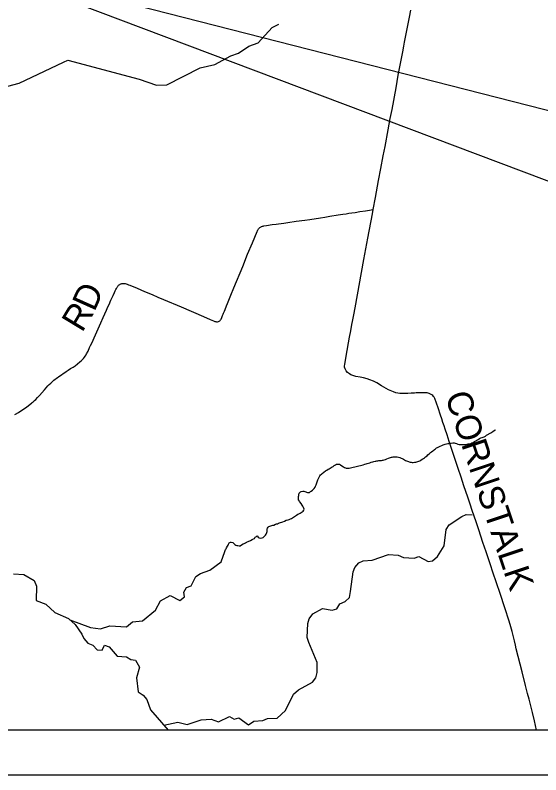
# Model space of a CAD drawing. Extents: x -19.5 to 44.1, y 0 to 22.
# Drawn here: x 5.392 to 6.569, y 14.347 to 16.047 of the extents above; entities that cross this region are included whole.
import ezdxf

# ---------------------------------------------------------------- set-up
doc = ezdxf.new("R2010")
doc.units = 0
for name, color, linetype in [('GM_X_Minor_River', 7, 'Continuous'), ('GM_X_Township_Road', 7, 'Continuous'), ('GM_X_Township_Road_Text', 7, 'Continuous'), ('SH_Data', 7, 'Continuous'), ('SH_Text', 7, 'Continuous')]:
    doc.layers.add(name, color=color, linetype=linetype)

msp = doc.modelspace()

# ---------------------------------------------------------------- linework, layer by layer
at = {"layer": 'GM_X_Minor_River'}
for points in [[(5.8753, 15.9562), (5.8924, 15.9617), (5.9155, 15.9779), (5.9366, 15.985), (5.9677, 16.0192), (5.9822, 16.0269)], [(5.1646, 15.8833), (5.2068, 15.901), (5.2193, 15.9), (5.2744, 15.8847), (5.3301, 15.8816), (5.3647, 15.8855), (5.4009, 15.8946), (5.5005, 15.9422), (5.5101, 15.9466), (5.6698, 15.9036), (5.709, 15.8906), (5.7318, 15.8909), (5.8065, 15.9292), (5.8393, 15.9365), (5.8753, 15.9562)], [(6.3064, 15.055), (6.309, 15.0569), (6.3109, 15.0588), (6.3144, 15.0614), (6.3163, 15.0633), (6.3194, 15.0655), (6.3224, 15.0682), (6.3243, 15.0697), (6.3274, 15.072), (6.3293, 15.0738), (6.3312, 15.0753), (6.3335, 15.0768), (6.3358, 15.0787), (6.3377, 15.0799), (6.3411, 15.0814), (6.3438, 15.0825), (6.3472, 15.084), (6.3503, 15.0855), (6.3526, 15.0862), (6.3552, 15.087), (6.3606, 15.0884), (6.3632, 15.0888), (6.3655, 15.0895), (6.3682, 15.0895), (6.3724, 15.0899), (6.375, 15.0899), (6.3773, 15.0891), (6.3803, 15.0883), (6.383, 15.0875), (6.386, 15.0867), (6.3879, 15.0863), (6.3906, 15.0863), (6.3948, 15.0863), (6.3974, 15.0867), (6.4009, 15.0866), (6.4039, 15.0874), (6.4062, 15.0877), (6.4081, 15.0877), (6.4123, 15.0888), (6.4146, 15.09), (6.4176, 15.0911), (6.4207, 15.093), (6.4234, 15.0945), (6.426, 15.096), (6.4291, 15.0978), (6.4321, 15.0997), (6.4348, 15.1012), (6.4375, 15.1023), (6.4398, 15.1031), (6.442, 15.1038), (6.4451, 15.1053), (6.4478, 15.1076), (6.4569, 15.1128), (6.4596, 15.1143), (6.4619, 15.1155), (6.4646, 15.1177), (6.4665, 15.1189), (6.4669, 15.1188)], [(6.0446, 14.9797), (6.0469, 14.9793), (6.0488, 14.9793), (6.0511, 14.9793), (6.0534, 14.9812), (6.0553, 14.9819), (6.058, 14.9845), (6.0614, 14.9879), (6.0637, 14.9906), (6.0649, 14.9929), (6.0664, 14.9959), (6.0672, 14.9985), (6.068, 15.0027), (6.0695, 15.0073), (6.0711, 15.0107), (6.073, 15.0133), (6.0745, 15.016), (6.0757, 15.0183), (6.078, 15.0198), (6.0799, 15.0213), (6.0868, 15.0277), (6.0898, 15.0292), (6.0929, 15.0311), (6.0952, 15.0322), (6.0975, 15.0337), (6.0998, 15.0348), (6.102, 15.0363), (6.104, 15.0374), (6.1066, 15.0393), (6.1097, 15.0412), (6.112, 15.0423), (6.1154, 15.0427), (6.1181, 15.0423), (6.1203, 15.0411), (6.1234, 15.0388), (6.1271, 15.0361), (6.1294, 15.035), (6.1317, 15.0342), (6.1336, 15.0338), (6.1366, 15.0334), (6.1397, 15.0338), (6.1427, 15.0345), (6.1458, 15.0349), (6.1492, 15.036), (6.153, 15.0367), (6.1583, 15.0378), (6.1618, 15.0385), (6.1656, 15.0397), (6.1686, 15.0404), (6.1717, 15.0411), (6.1747, 15.0423), (6.1778, 15.043), (6.18, 15.0437), (6.1865, 15.0456), (6.1896, 15.0467), (6.193, 15.0474), (6.1949, 15.0482), (6.1979, 15.0489), (6.1999, 15.0493), (6.2021, 15.0497), (6.2044, 15.05), (6.2067, 15.0504), (6.2086, 15.0508), (6.2124, 15.0507), (6.2143, 15.0511), (6.2162, 15.0515), (6.2185, 15.0522), (6.2216, 15.0529), (6.2242, 15.0541), (6.2277, 15.0556), (6.2303, 15.0567), (6.2322, 15.0574), (6.2345, 15.0582), (6.2364, 15.0582), (6.2383, 15.0585), (6.2402, 15.0589), (6.2429, 15.0589), (6.2452, 15.0585), (6.2474, 15.0585), (6.2505, 15.0581), (6.2531, 15.0573), (6.2566, 15.0561), (6.2584, 15.0553), (6.2619, 15.0534), (6.2637, 15.0523), (6.2664, 15.0507), (6.2683, 15.0499), (6.2706, 15.0492), (6.2763, 15.0472), (6.2789, 15.0468), (6.2812, 15.0464), (6.2831, 15.0464), (6.2861, 15.0468), (6.2896, 15.0471), (6.2915, 15.0475), (6.2938, 15.0482), (6.296, 15.049), (6.2983, 15.0497), (6.3006, 15.0512), (6.3037, 15.0535), (6.3064, 15.055)], [(5.8532, 14.8236), (5.862, 14.8472), (5.8635, 14.8514), (5.8647, 14.8533), (5.8655, 14.8552), (5.8674, 14.8586), (5.8689, 14.8612), (5.8697, 14.8635), (5.8716, 14.8661), (5.8743, 14.8676), (5.8762, 14.8676), (5.8796, 14.8668), (5.8823, 14.8642), (5.8842, 14.8626), (5.8864, 14.8611), (5.8883, 14.8603), (5.891, 14.8603), (5.8936, 14.8599), (5.8959, 14.8599), (5.899, 14.8621), (5.9024, 14.864), (5.9051, 14.8651), (5.9078, 14.8666), (5.9104, 14.8678), (5.9142, 14.8696), (5.9188, 14.8715), (5.923, 14.8741), (5.9261, 14.8756), (5.9283, 14.8764), (5.9299, 14.8794), (5.9322, 14.8809), (5.9341, 14.8817), (5.936, 14.8794), (5.9386, 14.8774), (5.9424, 14.8767), (5.9451, 14.8778), (5.9474, 14.8781), (5.9497, 14.8808), (5.9524, 14.8834), (5.9539, 14.8861), (5.9554, 14.8895), (5.9562, 14.8921), (5.9562, 14.8948), (5.9566, 14.8967), (5.9574, 14.8994), (5.9586, 14.9016), (5.9605, 14.9031), (5.9624, 14.9039), (5.9647, 14.9042), (5.9666, 14.905), (5.9692, 14.9057), (5.9711, 14.9061), (5.9749, 14.908), (5.9776, 14.9087), (5.9795, 14.9091), (5.9818, 14.9102), (5.9841, 14.911), (5.9864, 14.9117), (5.989, 14.9124), (5.9917, 14.9136), (5.9951, 14.9151), (5.999, 14.9169), (6.0035, 14.9177), (6.0058, 14.9188), (6.0085, 14.9199), (6.0112, 14.921), (6.0134, 14.9221), (6.0154, 14.9237), (6.0177, 14.9252), (6.0222, 14.9285), (6.0253, 14.9304), (6.0272, 14.9316), (6.0306, 14.933), (6.0329, 14.9342), (6.0348, 14.9361), (6.0367, 14.9376), (6.0387, 14.9398), (6.0391, 14.9421), (6.0376, 14.9455), (6.0361, 14.9486), (6.0346, 14.9509), (6.0323, 14.9543), (6.0297, 14.9578), (6.0285, 14.9597), (6.0263, 14.9623), (6.0267, 14.9646), (6.0267, 14.9673), (6.0267, 14.9699), (6.0271, 14.9726), (6.0275, 14.9753), (6.0283, 14.9775), (6.0309, 14.9802), (6.0329, 14.9813), (6.0359, 14.982), (6.0386, 14.982), (6.0405, 14.9813), (6.0427, 14.9805), (6.0446, 14.9797)], [(5.8473, 14.4661), (5.8721, 14.4775), (5.8822, 14.472), (5.8929, 14.4751), (5.9149, 14.4594), (5.9269, 14.4675), (5.947, 14.4689), (5.957, 14.4733), (5.9786, 14.4739), (5.9972, 14.4913), (6.0151, 14.5278), (6.0263, 14.5378), (6.0577, 14.5545), (6.0652, 14.5646), (6.0685, 14.5759), (6.0682, 14.5983), (6.0498, 14.6436), (6.0462, 14.6543), (6.0473, 14.6862), (6.0505, 14.6964), (6.0587, 14.7076), (6.0803, 14.7196), (6.1022, 14.7157), (6.1125, 14.7185), (6.1188, 14.7301), (6.1307, 14.7352), (6.1411, 14.7441), (6.1429, 14.7573), (6.1488, 14.8012), (6.1528, 14.8114), (6.1614, 14.8215), (6.1717, 14.8262), (6.1918, 14.8276), (6.2278, 14.8404), (6.2494, 14.8388), (6.2614, 14.8339), (6.2739, 14.8325), (6.2857, 14.8322), (6.296, 14.8358), (6.317, 14.8247), (6.3269, 14.826), (6.3374, 14.836), (6.3527, 14.8595), (6.3572, 14.8963), (6.3635, 14.9068), (6.3924, 14.9251), (6.402, 14.9298), (6.4152, 14.9287)], [(5.5147, 14.6942), (5.5608, 14.6767), (5.5831, 14.6736), (5.6041, 14.6807), (5.6413, 14.6788), (5.6552, 14.6899), (5.6772, 14.6917), (5.7065, 14.7154), (5.7176, 14.7368), (5.7391, 14.7489), (5.7612, 14.737), (5.7716, 14.7452), (5.7696, 14.7562), (5.7762, 14.7664), (5.7861, 14.7699), (5.7968, 14.791), (5.8072, 14.798), (5.8278, 14.8052), (5.8532, 14.8236)], [(5.3882, 14.7967), (5.4117, 14.7955), (5.4346, 14.782), (5.4397, 14.7698), (5.439, 14.7371), (5.4613, 14.729), (5.4814, 14.7104), (5.5119, 14.6968), (5.5264, 14.6839), (5.5419, 14.6623), (5.5459, 14.652), (5.5552, 14.6419), (5.5665, 14.6375), (5.5758, 14.627), (5.5872, 14.6264), (5.5923, 14.6373), (5.6025, 14.6337), (5.6207, 14.6131), (5.6415, 14.6115), (5.6513, 14.6056), (5.6618, 14.6035), (5.6707, 14.5885), (5.6641, 14.5643), (5.6673, 14.5331), (5.6785, 14.5256), (5.6871, 14.5155), (5.695, 14.4926), (5.7347, 14.4473)], [(5.7253, 14.4581), (5.7563, 14.465), (5.7771, 14.46), (5.8084, 14.4704), (5.8308, 14.4718), (5.8473, 14.4661)]]:
    msp.add_lwpolyline(points, dxfattribs=at)
at = {"layer": 'GM_X_Township_Road'}
for points in [[(6.1939, 15.612), (6.1991, 15.6392), (6.206, 15.6771), (6.211, 15.7039), (6.2164, 15.732), (6.2204, 15.7534), (6.2273, 15.7906), (6.2321, 15.8156), (6.236, 15.8358), (6.2449, 15.8847), (6.25, 15.9127), (6.2557, 15.9426), (6.2602, 15.9651), (6.2627, 15.9779), (6.2642, 15.9865), (6.2656, 15.9944), (6.2749, 16.0425), (6.2779, 16.0583)], [(5.8474, 15.3618), (5.8487, 15.3625), (5.8501, 15.3632), (5.8512, 15.364), (5.8521, 15.3651), (5.8527, 15.3659), (5.8533, 15.367), (5.8547, 15.3703), (5.8567, 15.3749), (5.8579, 15.3778), (5.8588, 15.3801), (5.8606, 15.3848), (5.8622, 15.3888), (5.8655, 15.3969), (5.8676, 15.4021), (5.8752, 15.4205), (5.8819, 15.4372), (5.9016, 15.4849), (5.9127, 15.5126), (5.9233, 15.5377), (5.9338, 15.563), (5.9347, 15.5648), (5.9356, 15.5667), (5.9362, 15.5678), (5.9371, 15.5691), (5.9384, 15.5706), (5.9398, 15.5717), (5.9412, 15.5726), (5.9428, 15.5735), (5.9441, 15.5741), (5.9457, 15.5748), (5.9472, 15.5752), (5.9487, 15.5756), (5.9546, 15.5767), (5.9675, 15.5784), (5.9767, 15.5795), (5.9816, 15.5802), (5.9878, 15.581), (5.994, 15.5819), (6.0026, 15.5831), (6.0216, 15.5858), (6.0407, 15.5885), (6.0518, 15.5901), (6.0758, 15.5937), (6.0856, 15.5952), (6.0966, 15.597), (6.1151, 15.6), (6.1255, 15.6017), (6.1335, 15.6029), (6.1396, 15.6038), (6.1457, 15.6047), (6.1531, 15.6059), (6.1641, 15.6077), (6.1764, 15.6095), (6.1812, 15.6102), (6.1939, 15.612)], [(6.5595, 14.4473), (6.5549, 14.4681), (6.5504, 14.4868), (6.5426, 14.5169), (6.5392, 14.5291), (6.5349, 14.5471), (6.5274, 14.5775), (6.5141, 14.6294), (6.5122, 14.6372), (6.5099, 14.6471), (6.5051, 14.6682), (6.5022, 14.6784), (6.4982, 14.6914), (6.4885, 14.721), (6.4779, 14.7528), (6.4619, 14.8005), (6.4562, 14.8169), (6.4464, 14.8464), (6.4394, 14.8669), (6.4303, 14.8955), (6.4241, 14.9136), (6.4155, 14.9388), (6.4108, 14.9529), (6.4056, 14.9688), (6.397, 14.9941), (6.3905, 15.0135), (6.3842, 15.0324), (6.3803, 15.0442), (6.376, 15.0571), (6.3684, 15.0795), (6.3639, 15.0935), (6.3593, 15.1081), (6.3549, 15.121), (6.3525, 15.1283), (6.35, 15.136), (6.3472, 15.1441), (6.3447, 15.1524), (6.3393, 15.1683), (6.3321, 15.1892), (6.3306, 15.1921), (6.329, 15.1941), (6.3272, 15.1959), (6.3251, 15.1975), (6.3235, 15.1985), (6.3224, 15.1991), (6.3207, 15.1999), (6.319, 15.2006), (6.3172, 15.2011), (6.3148, 15.2017), (6.3123, 15.2021), (6.3098, 15.2023), (6.306, 15.2024), (6.2942, 15.202), (6.2899, 15.2018), (6.2862, 15.2015), (6.2788, 15.2011), (6.2715, 15.2008), (6.2642, 15.2005), (6.2611, 15.2005), (6.2574, 15.2005), (6.2532, 15.2008), (6.2492, 15.2013), (6.2441, 15.2024), (6.2396, 15.2039), (6.2355, 15.2055), (6.2283, 15.209), (6.2123, 15.218), (6.2018, 15.2242), (6.1941, 15.228), (6.1862, 15.2313), (6.1801, 15.2335), (6.1723, 15.2356), (6.1647, 15.2372), (6.1552, 15.2389), (6.1502, 15.2401), (6.1439, 15.2424), (6.1404, 15.2444), (6.1364, 15.2479), (6.1336, 15.251), (6.1323, 15.253), (6.1308, 15.2557), (6.1298, 15.2591), (6.1297, 15.2625), (6.13, 15.2657), (6.1334, 15.2843), (6.1411, 15.3269), (6.1435, 15.3408), (6.1462, 15.3548), (6.1473, 15.3616), (6.1503, 15.3769), (6.1531, 15.3922), (6.1727, 15.5001), (6.182, 15.5482), (6.1922, 15.6026), (6.1939, 15.612)], [(5.4053, 15.1616), (5.4129, 15.1669), (5.4185, 15.1707), (5.4288, 15.1786), (5.4307, 15.1801), (5.4328, 15.1819), (5.4358, 15.1848), (5.4385, 15.1873), (5.4425, 15.1915), (5.4468, 15.1962), (5.4579, 15.2089), (5.4616, 15.2131), (5.4655, 15.2175), (5.4687, 15.2206), (5.4722, 15.224), (5.4754, 15.227), (5.4791, 15.2301), (5.487, 15.236), (5.4896, 15.2377), (5.5068, 15.2494), (5.5112, 15.2524), (5.5165, 15.2562), (5.5219, 15.2598), (5.5264, 15.2628), (5.5315, 15.2667), (5.5374, 15.2713), (5.5397, 15.2733), (5.5421, 15.2756), (5.5449, 15.2788), (5.5472, 15.2817), (5.5492, 15.2843), (5.5509, 15.2869), (5.5522, 15.2891), (5.5554, 15.2952), (5.559, 15.3031), (5.5613, 15.3082), (5.5636, 15.3133), (5.5722, 15.3318), (5.5841, 15.3584), (5.5896, 15.3707), (5.5969, 15.3869), (5.6001, 15.3941), (5.6025, 15.3997), (5.6067, 15.4091), (5.6096, 15.4154), (5.6115, 15.4197), (5.6146, 15.4266), (5.6162, 15.4303), (5.6178, 15.4335), (5.6188, 15.4354), (5.6198, 15.4372), (5.6207, 15.4386), (5.6212, 15.4395), (5.6219, 15.4405), (5.6229, 15.4417), (5.6239, 15.4428), (5.6251, 15.4439), (5.6264, 15.4447), (5.6275, 15.4453), (5.6285, 15.4457), (5.6295, 15.4462), (5.6308, 15.4465), (5.6319, 15.4468), (5.633, 15.4469), (5.6341, 15.4469), (5.6353, 15.4469), (5.6367, 15.4467), (5.6382, 15.4465), (5.6405, 15.4458), (5.6428, 15.4451), (5.6463, 15.4438), (5.6492, 15.4427), (5.6653, 15.4359), (5.6817, 15.4288), (5.699, 15.4218), (5.712, 15.4164), (5.7242, 15.4112), (5.7636, 15.3944), (5.8139, 15.3729), (5.8286, 15.3664), (5.8361, 15.3633), (5.8381, 15.3624), (5.8394, 15.362), (5.8404, 15.3617), (5.8416, 15.3614), (5.8428, 15.3612), (5.8439, 15.3611), (5.8452, 15.3612), (5.8474, 15.3618)], [(5.3915, 15.1534), (5.3932, 15.1545), (5.3995, 15.1582), (5.4053, 15.1616)]]:
    msp.add_lwpolyline(points, dxfattribs=at)
at = {"layer": 'SH_Data'}
for p, q in [((9.4, 14.4473), (2.6, 14.4473)), ((2.5, 14.3473), (9.5, 14.3473))]:
    msp.add_line(p, q, dxfattribs=at)
at = {"layer": 'SH_Text'}
msp.add_lwpolyline([(6.926, 15.5471), (5.2798, 16.1676), (6.926, 15.7471)], close=True, dxfattribs=at)

# ---------------------------------------------------------------- texts
at = {"layer": 'GM_X_Township_Road_Text'}
for s, height, rotation, p in [('D', 0.0568, 65.8484, (5.5696, 15.3818)), ('R', 0.0568, 58.7782, (5.5419, 15.3352)), ('CORNSTALK', 0.05682, 288.4704, (6.3541, 15.1955))]:
    msp.add_text(s, height=height, rotation=rotation, dxfattribs=at).set_placement(p)

doc.saveas('drawing.dxf')
